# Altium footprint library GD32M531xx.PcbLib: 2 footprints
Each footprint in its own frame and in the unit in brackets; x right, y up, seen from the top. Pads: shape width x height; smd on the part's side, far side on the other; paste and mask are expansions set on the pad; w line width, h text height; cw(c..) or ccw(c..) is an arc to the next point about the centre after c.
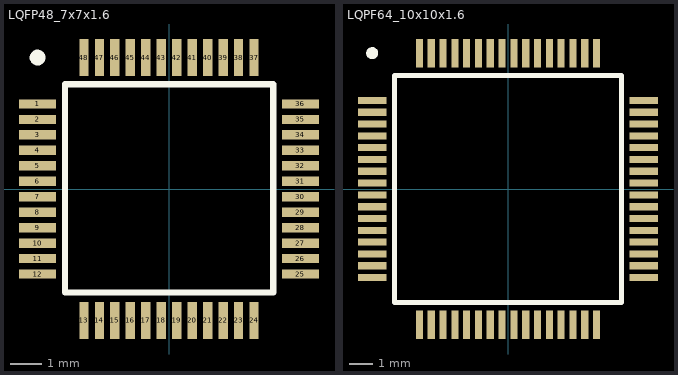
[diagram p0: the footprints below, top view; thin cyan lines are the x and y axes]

## LQFP48_7x7x1.6 [mm]
pads (48):
  rect 1.2x0.3 smd: 1(-4.25,2.75) 2(-4.25,2.25) 3(-4.25,1.75) 4(-4.25,1.25) 5(-4.25,0.75) 6(-4.25,0.25) 7(-4.25,-0.25) 8(-4.25,-0.75) 9(-4.25,-1.25) 10(-4.25,-1.75) 11(-4.25,-2.25) 12(-4.25,-2.75) 25(4.25,-2.75) 26(4.25,-2.25) 27(4.25,-1.75) 28(4.25,-1.25) 29(4.25,-0.75) 30(4.25,-0.25) 31(4.25,0.25) 32(4.25,0.75) 33(4.25,1.25) 34(4.25,1.75) 35(4.25,2.25) 36(4.25,2.75)
  rect 0.3x1.2 smd: 13(-2.75,-4.25) 14(-2.25,-4.25) 15(-1.75,-4.25) 16(-1.25,-4.25) 17(-0.75,-4.25) 18(-0.25,-4.25) 19(0.25,-4.25) 20(0.75,-4.25) 21(1.25,-4.25) 22(1.75,-4.25) 23(2.25,-4.25) 24(2.75,-4.25) 37(2.75,4.25) 38(2.25,4.25) 39(1.75,4.25) 40(1.25,4.25) 41(0.75,4.25) 42(0.25,4.25) 43(-0.25,4.25) 44(-0.75,4.25) 45(-1.25,4.25) 46(-1.75,4.25) 47(-2.25,4.25) 48(-2.75,4.25)
Top Overlay:
  circle w0.254: c-4.25,4.25 r0.127
  lines w0.203: -3.361,-3.346 -3.361,3.385 3.37,3.385 3.37,-3.346 -3.361,-3.346
3D body "TSQFP50P900X900X160-48N.step": height 1.6, standoff 0, extent -4.5,-4.5 4.5,4.5

## LQPF64_10x10x1.6 [mm]
pads (64):
  rect 1.2x0.3 smd: 1(-5.75,3.75) 2(-5.75,3.25) 3(-5.75,2.75) 4(-5.75,2.25) 5(-5.75,1.75) 6(-5.75,1.25) 7(-5.75,0.75) 8(-5.75,0.25) 9(-5.75,-0.25) 10(-5.75,-0.75) 11(-5.75,-1.25) 12(-5.75,-1.75) 13(-5.75,-2.25) 14(-5.75,-2.75) 15(-5.75,-3.25) 16(-5.75,-3.75) 33(5.75,-3.75) 34(5.75,-3.25) 35(5.75,-2.75) 36(5.75,-2.25) 37(5.75,-1.75) 38(5.75,-1.25) 39(5.75,-0.75) 40(5.75,-0.25) 41(5.75,0.25) 42(5.75,0.75) 43(5.75,1.25) 44(5.75,1.75) 45(5.75,2.25) 46(5.75,2.75) 47(5.75,3.25) 48(5.75,3.75)
  rect 0.3x1.2 smd: 17(-3.75,-5.75) 18(-3.25,-5.75) 19(-2.75,-5.75) 20(-2.25,-5.75) 21(-1.75,-5.75) 22(-1.25,-5.75) 23(-0.75,-5.75) 24(-0.25,-5.75) 25(0.25,-5.75) 26(0.75,-5.75) 27(1.25,-5.75) 28(1.75,-5.75) 29(2.25,-5.75) 30(2.75,-5.75) 31(3.25,-5.75) 32(3.75,-5.75) 49(3.75,5.75) 50(3.25,5.75) 51(2.75,5.75) 52(2.25,5.75) 53(1.75,5.75) 54(1.25,5.75) 55(0.75,5.75) 56(0.25,5.75) 57(-0.25,5.75) 58(-0.75,5.75) 59(-1.25,5.75) 60(-1.75,5.75) 61(-2.25,5.75) 62(-2.75,5.75) 63(-3.25,5.75) 64(-3.75,5.75)
Top Overlay:
  circle w0.254: c-5.75,5.75 r0.127
  lines w0.203: -4.801,-4.801 -4.801,4.801 4.801,4.801 4.801,-4.801 -4.801,-4.801
3D body "TSQFP50P1200X1200X160-64N.step": height 1.6, standoff 0, extent -6,-6 6,6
